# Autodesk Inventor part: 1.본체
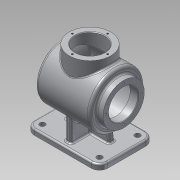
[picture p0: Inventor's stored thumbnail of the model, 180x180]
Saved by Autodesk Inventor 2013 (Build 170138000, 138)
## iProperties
Created: 2016-09
Part Number: 1.본체
Material: 알루미늄 6061
Document SubType Name: Modeling
Designer: default
Density: 2.71 g/cm^3
Mass: 972.439 g
Surface Area: 1283.07 cm^2
Volume: 358.834 cm^3
Author: default
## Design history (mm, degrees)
sketch "스케치1"
  geometry: L1 (-67.5, -50)-(67.5, -50); L2 (67.5, -50)-(67.5, 50); L3 (67.5, 50)-(-67.5, 50); L4 (-67.5, 50)-(-67.5, -50); L5 (-67.5, -50)-(67.5, 50); L6 (67.5, -50)-(-67.5, 50); 1 further point
  constraints: 12 end point, 2 midpoint, 2 parallel, 1 horizontal, 1 perpendicular
  dimensions: "d0" = 100 distance of L1.end L2.end; "d2" = 135 distance of L2.end L3.end
extrude "돌출1" new body sketch "스케치1" distance "d3" = 10; taper "d4" = 0 deg
sketch "스케치2"
  geometry: L1 (67.5, 0)-(-67.5, 0) reference; L2 (60, 82)-(-62, 82); L3 (48.562, 132)-(-50, 132); L4 (-50, 132)-(-50, 120); L5 (-50, 120)-(-62, 120); L6 (-62, 120)-(-62, 82); A1 r 115 centre (-55, 82) between (60, 82) and (48.562, 132); 1 further point
  constraints: 10 end point, 4 parallel, 2 point on circle, 1 centre point, 1 horizontal alignment, 1 perpendicular
  dimensions: "d5" = 76 diameter of L5 L2; "d8" = 100 diameter of L3 L2; "d9" = 12 distance between parallel lines of L4 L6; "d11" = 82 distance from line of L1 L2.end; "d13" = 50 distance from line of point (0, 0) L4; "d14" = 230 diameter of A1; "d15" = 110 distance from line of L4 L2.start
revolve "회전1" sketch "스케치2" stored, may be unused: angle "d16" = 90 deg
sketch "스케치3"
  geometry: L1 (-62, 44)-(-62, 120) reference; L2 (-62, 82)-(60, 82); L3 (-62, 109)-(-47, 109); L4 (-47, 109)-(-47, 127); L5 (-45, 129)-(46.661, 129); A1 r 115 centre (-55, 82) between (48.562, 32) and (48.562, 132) reference; A2 r 112 centre (-55, 82) between (57, 82) and (46.661, 129); A3 r 2 centre (-45, 127) between (-45, 129) and (-47, 127); 2 further points
  constraints: 8 end point, 5 point on circle, 4 point on line, 2 centre point, 2 parallel, 2 tangent, 1 midpoint, 1 perpendicular
  dimensions: "d17" = 3 radial gap between concentric circles of A1 A2; "d18" = 94 diameter of L5 L2; "d19" = 54 diameter of L3 L2; "d20" = 15 distance between parallel lines of L1 L4; "d38" = 2 radius of A3
revolve "회전2" sketch "스케치3" stored, may be unused: angle "d21" = 90 deg
node "작업 평면1"
sketch "스케치4"
  geometry: L1 (50, 50)-(50, -50) reference; C1 r 38 at (0, 0); 2 further points
  constraints: 1 centre point, 1 horizontal alignment, 1 midpoint
  dimensions: "d23" = 76 diameter of C1; "d24" = 50 distance from line of L1 C1.centre
extrude "돌출2" join sketch "스케치4" stored distance "d25" = 10; taper "d26" = 0 deg
sketch "스케치5"
  geometry: C1 r 38 at (0, 0) reference; C2 r 27 at (0, 0); 1 further point
  constraints: 1 centre point, 1 coincident
  dimensions: "d27" = 54 diameter of C2
extrude "돌출3" cut sketch "스케치5" stored distance "d28" = 10; taper "d29" = 0 deg
sketch "스케치7"
  geometry: C1 r 27 at (0, 0) reference; 2 further points
  constraints: 1 horizontal alignment
  dimensions: "d30" = 32.5 distance of C1.centre point (-32.5, 0)
hole "구멍1" sketch "스케치7" at (-32.5, 0) diameter "d31" = 3.242; stored, may be unused: countersink angle "d35" = 90 deg, drill point angle "d37" = 118 deg; dims "d32" = 8, "d33" = 4, "d34" = 2, "d36" = 10
fillet "모깎기1" dims "d39" = 2
sketch "스케치9"
  geometry: C1 r 27 at (0, 0) reference; 1 further point
  constraints: 1 horizontal alignment
  dimensions: "d43" = 32.5 distance of C1.centre point (-32.5, 0)
hole "구멍2" sketch "스케치9" at (-32.5, 0) diameter "d44" = 3.242; stored, may be unused: countersink angle "d48" = 90 deg, drill point angle "d50" = 118 deg; dims "d45" = 8, "d46" = 4, "d47" = 2, "d49" = 10
chamfer "모따기1" distance "d54" = 1; stored, may be unused: second distance "d55" = 2, angle "d56" = 45 deg
sketch "스케치10"
  geometry: L1 (-50, 10)-(50, 10) reference; L2 (40, 52)-(40, 10); L3 (-40, 10)-(-40, 52); L4 (-40, 10)-(40, 10); A1 r 50 centre (0, 82) between (40, 52) and (-40, 52) reference; 1 further point
  constraints: 6 end point, 2 point on circle, 2 point on line, 1 collinear, 1 parallel, 1 perpendicular
  dimensions: "d57" = 40 distance from line of point (0, 0) L2; "d58" = 40 distance from line of point (0, 0) L3
extrude "돌출4" join sketch "스케치10" stored distance "d59" = 10; taper "d60" = 0 deg
sketch "스케치11"
  geometry: L1 (-50, 32)-(48.562, 32) reference; L2 (67.5, 0)-(-67.5, 0) reference; L3 (-67.5, 0)-(-67.5, 10) reference; L4 (67.5, 10)-(-67.5, 10) reference; L5 (67.5, 0)-(67.5, 10) reference; L6 (67.5, 10)-(-67.5, 10) reference; L7 (-38.075, 32)-(-40, 10); 1 further point
  constraints: 2 end point, 2 point on line
  dimensions: "d61" = 95 deg angle of L4 L7; "d62" = 40 horizontal distance of point (0, 0) L7.end
feature "리브1" sketch "스케치11" dims "d63" = 1, "d64" = 10, "d65" = 0, "d66" = 0, "d67" = 1, "d68" = 1
sketch "스케치12"
  geometry: L1 (-50, 32)-(48.562, 32) reference; L2 (67.5, 10)-(-67.5, 10) reference; L3 (40, 10)-(38.075, 32); 1 further point
  constraints: 2 end point, 2 point on line
  dimensions: "d69" = 95 deg angle of L2 L3; "d70" = 40 horizontal distance of point (0, 0) L3.start
feature "리브2" sketch "스케치12" dims "d71" = 1, "d72" = 10, "d73" = 0, "d74" = 0, "d75" = 1, "d76" = 1
fillet "모깎기2" dims "d77" = 5
fillet "모깎기3" dims "d78" = 15
sketch "스케치14"
  geometry: A1 r 15 centre (52.5, -35) between (52.5, -50) and (67.5, -35) reference; A2 r 15 centre (52.5, 35) between (67.5, 35) and (52.5, 50) reference; A3 r 15 centre (-52.5, 35) between (-52.5, 50) and (-67.5, 35) reference; A4 r 15 centre (-52.5, -35) between (-67.5, -35) and (-52.5, -50) reference; 1 further point
hole "구멍3" sketch "스케치14" at (-52.5, 35), (52.5, 35), (52.5, -35), (-52.5, -35) diameter "d79" = 10; stored, may be unused: countersink angle "d83" = 90 deg, drill point angle "d85" = 0 deg; dims "d80" = 8, "d81" = 4, "d82" = 2, "d84" = 10
fillet "모깎기4" dims "d86" = 3
fillet "모깎기5" dims "d87" = 3
fillet "모깎기6" dims "d88" = 3
node "작업 평면2"
sketch "스케치15"
  geometry: L1 (-40, 51.016)-(-40, 13) reference; L2 (-35, 0)-(35, 0) reference; 2 further points
  constraints: 1 other
  dimensions: "d90" = 82 distance from line of L2 point (0, 82); "d91" = 40 distance from line of L1 point (0, 82)
feature "엠보싱1" sketch "스케치15" dims "d0" = 100, "d2" = 135, "d92" = 0.5, "d93" = 0
node "솔리드1"
pattern_circular "원형 패턴1" dims angle "d41" = 360 deg
pattern_circular "원형 패턴2" dims angle "d52" = 360 deg
node "투영된 루프1"
other parameters: "d22" = 147
